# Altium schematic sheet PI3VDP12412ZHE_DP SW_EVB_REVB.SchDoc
size 513 x 386 mm
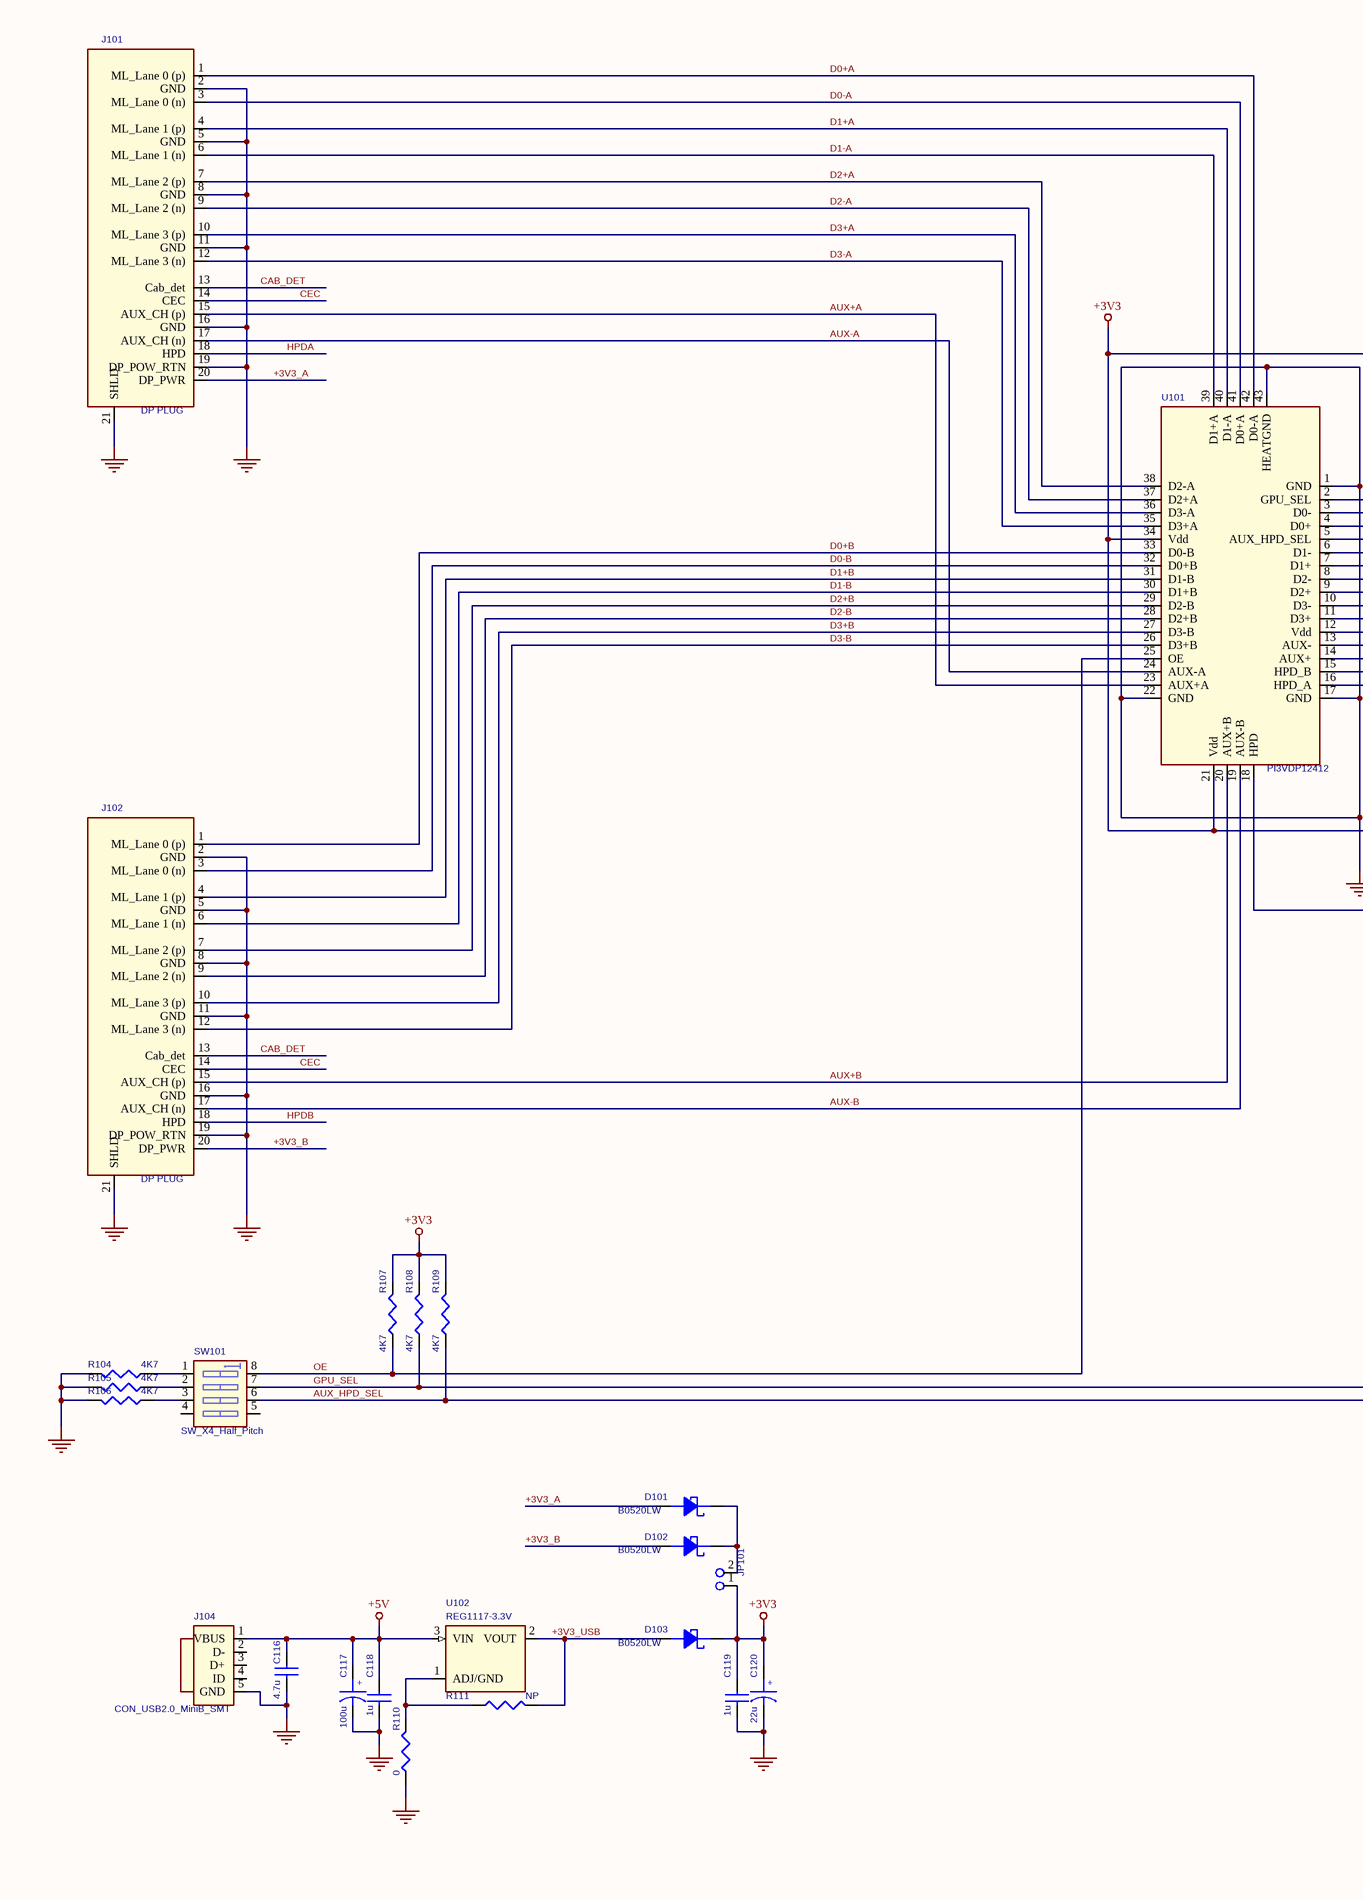
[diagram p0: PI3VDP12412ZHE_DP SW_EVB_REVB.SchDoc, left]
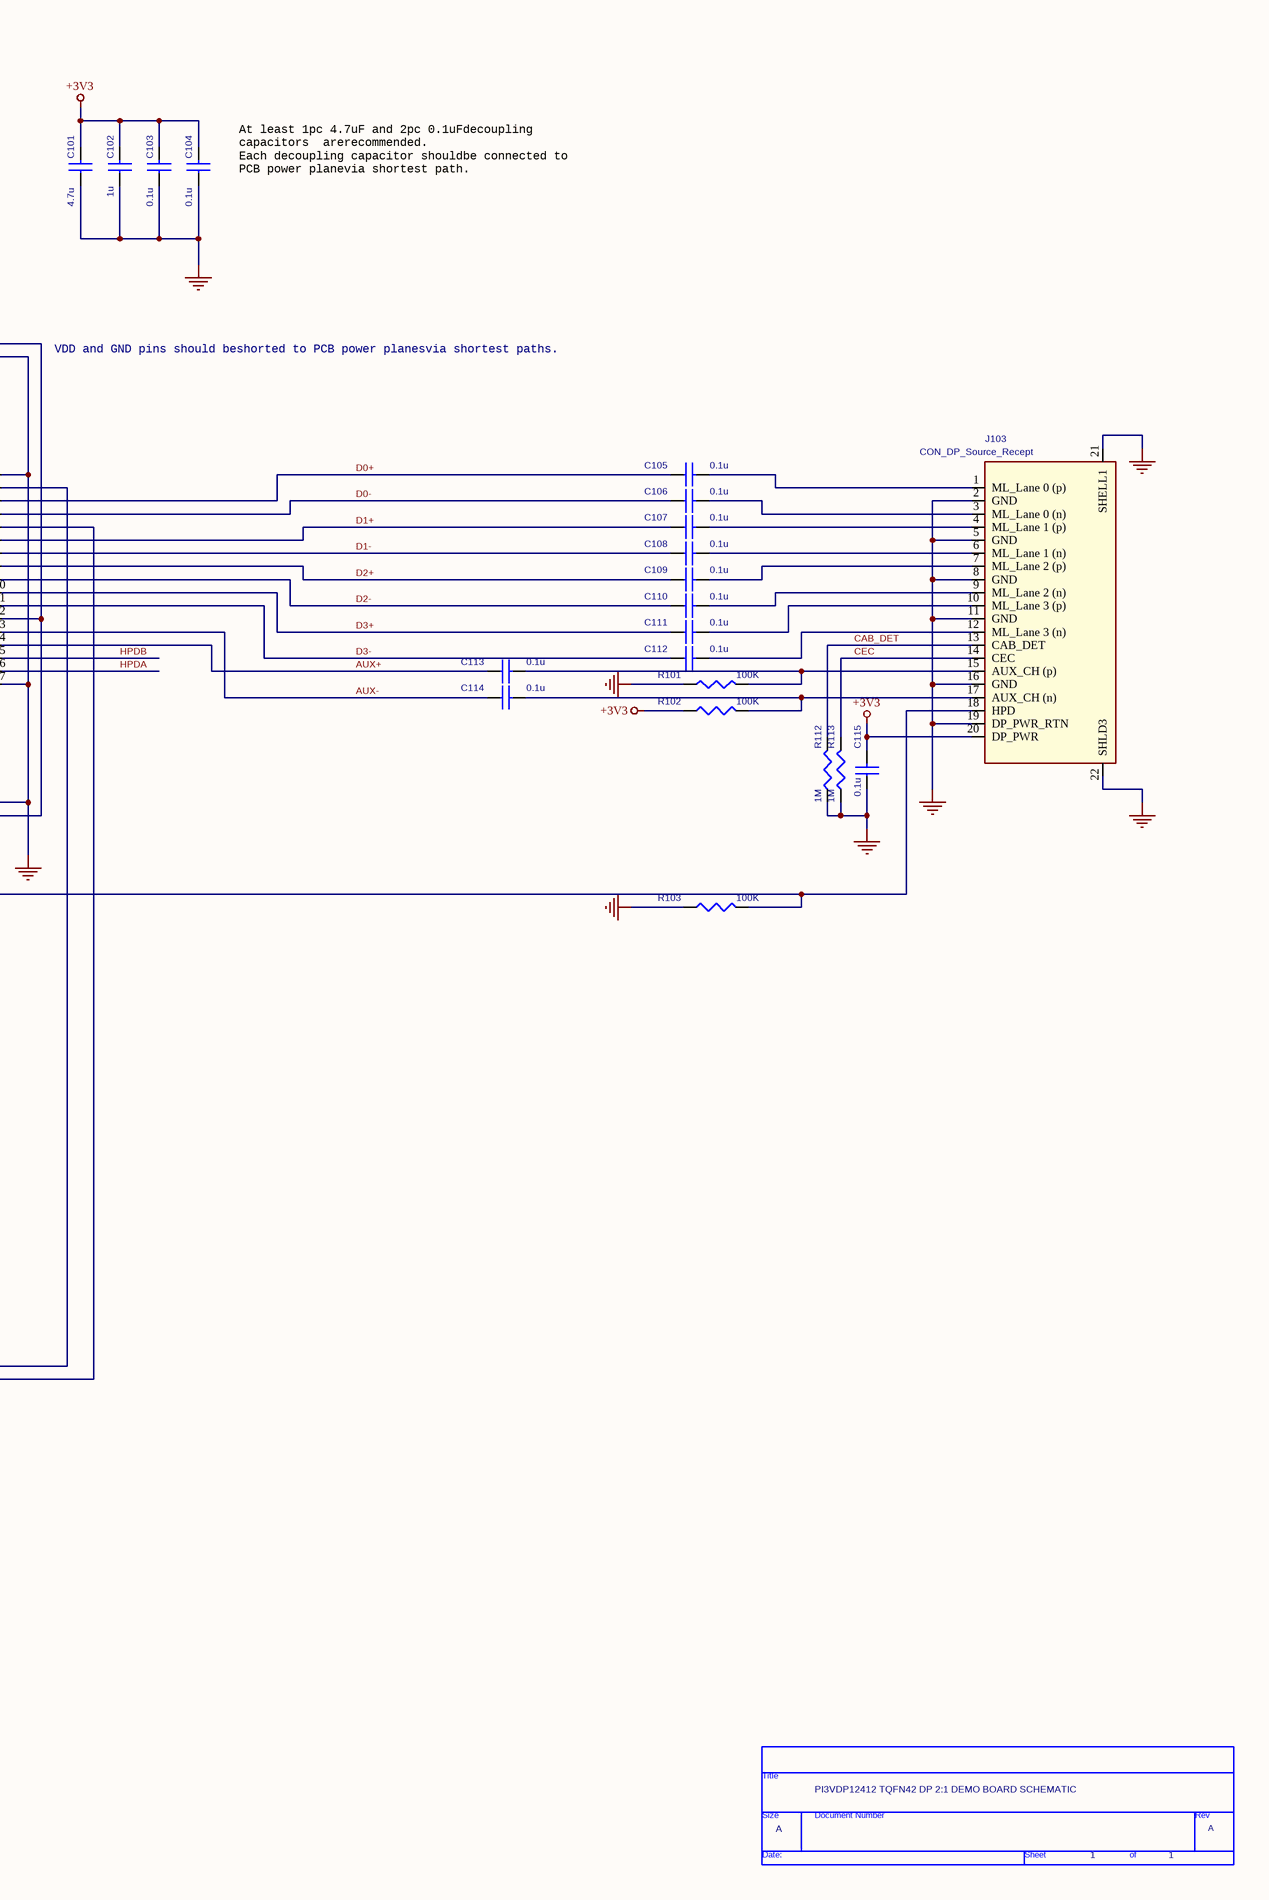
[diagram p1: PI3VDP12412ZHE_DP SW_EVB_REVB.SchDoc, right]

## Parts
*  Page Count: 1  Page Size: A  Title: PI3VDP12412 TQFN42 DP 2:1 DEMO BOARD SCHEMATIC  (hidden comment: TitleBlock0)  (graphical)
C101  4.7u  [CC_0402]
C102  1u  [CC_0402]
C103  0.1u  [CC_0402]
C104  0.1u  [CC_0402]
C105  0.1u  [CC_0402]
C106  0.1u  [CC_0402]
C107  0.1u  [CC_0402]
C108  0.1u  [CC_0402]
C109  0.1u  [CC_0402]
C110  0.1u  [CC_0402]
C111  0.1u  [CC_0402]
C112  0.1u  [CC_0402]
C113  0.1u  [CC_0402]
C114  0.1u  [CC_0402]
C115  0.1u  [CC_0402]
C116  4.7u  [CAP@CC_0805]
C117  100u  [CAP@CT_7343]
C118  1u  [CAP@CC_0805]
C119  1u  [CAP@CC_0805]
C120  22u  [CAP@CT_3528]
D101  B0520LW  [D@SOD-123]
D102  B0520LW  [D@SOD-123]
D103  B0520LW  [D@SOD-123]
J101  DP PLUG  [CON_DP_PLUG]
J102  DP PLUG  [CON_DP_PLUG]
J103  CON_DP_Source_Recept  [CON_DP_Recept]
J104  CON_USB2.0_MiniB_SMT  [CON_USB2.0_MiniB_SMT]
JP101  2x1 Pin Header  [2x1 Pin Header]  (value not drawn)
R101  100K  [R_0402]
R102  100K  [R_0402]
R103  100K  [R_0402]
R104  4K7  [R_0402]
R105  4K7  [R_0402]
R106  4K7  [R_0402]
R107  4K7  [RES@R_0402]
R108  4K7  [RES@R_0402]
R109  4K7  [RES@R_0402]
R110  0  [RES@R_0402]
R111  NP  [RES@R_0402]
R112  1M  [RES@R_0402]
R113  1M  [RES@R_0402]
SW101  SW_X4_Half_Pitch  [SW_X4_Half_Pitch]
U101  PI3VDP12412  [TQFN42]
U102  REG1117-3.3V  [Pow_SOT_89]

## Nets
+3V3: C101.2 C102.2 C103.2 C104.2 C115.2 C119.1 C120.1 D103.2 J103.20(DP_PWR) JP101.1 R102.1 R107.2 R108.2 R109.2 U101.12(Vdd) U101.21(Vdd) U101.34(Vdd)
+5V: C116.1 C117.1 C118.1 J104.1(VBUS) U102.3(VIN)
GND: C101.1 C102.1 C103.1 C104.1 C115.1 C116.2 C117.2 C118.2 C119.2 C120.2 J101.2(GND) J101.5(GND) J101.8(GND) J101.11(GND) J101.16(GND) J101.19(DP_POW_RTN) J101.21(SHLD) J102.2(GND) J102.5(GND) J102.8(GND) J102.11(GND) J102.16(GND) J102.19(DP_POW_RTN) J102.21(SHLD) J103.2(GND) J103.5(GND) J103.8(GND) J103.11(GND) J103.16(GND) J103.19(DP_PWR_RTN) J103.21(SHELL1) J103.22(SHLD3) J104.5(GND) R101.1 R103.1 R104.2 R105.2 R106.2 R110.1 R112.1 R113.1 U101.1(GND) U101.17(GND) U101.22(GND) U101.43(HEATGND)
+3V3_A: D101.1 J101.20(DP_PWR)
+3V3_B: D102.1 J102.20(DP_PWR)
+3V3_USB: D103.1 R111.2 U102.2(VOUT)
AUX+: C113.1 U101.14(AUX+)
AUX+A: J101.15(AUX_CH_(p)) U101.23(AUX+A)
AUX+B: J102.15(AUX_CH_(p)) U101.20(AUX+B)
AUX-: C114.1 U101.13(AUX-)
AUX-A: J101.17(AUX_CH_(n)) U101.24(AUX-A)
AUX-B: J102.17(AUX_CH_(n)) U101.19(AUX-B)
AUX_HPD_SEL: R109.1 SW101.6 U101.5(AUX_HPD_SEL)
CAB_DET: J101.13(Cab_det) J102.13(Cab_det) J103.13(CAB_DET) R112.2
CEC: J101.14(CEC) J102.14(CEC) J103.14(CEC) R113.2
D0+: C105.1 U101.3(D0-)
D0+A: J101.1(ML_Lane_0_(p)) U101.42(D0-A)
D0+B: J102.1(ML_Lane_0_(p)) U101.33(D0-B)
D0-: C106.1 U101.4(D0+)
D0-A: J101.3(ML_Lane_0_(n)) U101.41(D0+A)
D0-B: J102.3(ML_Lane_0_(n)) U101.32(D0+B)
D1+: C107.1 U101.6(D1-)
D1+A: J101.4(ML_Lane_1_(p)) U101.40(D1-A)
D1+B: J102.4(ML_Lane_1_(p)) U101.31(D1-B)
D1-: C108.1 U101.7(D1+)
D1-A: J101.6(ML_Lane_1_(n)) U101.39(D1+A)
D1-B: J102.6(ML_Lane_1_(n)) U101.30(D1+B)
D2+: C109.1 U101.8(D2-)
D2+A: J101.7(ML_Lane_2_(p)) U101.38(D2-A)
D2+B: J102.7(ML_Lane_2_(p)) U101.29(D2-B)
D2-: C110.1 U101.9(D2+)
D2-A: J101.9(ML_Lane_2_(n)) U101.37(D2+A)
D2-B: J102.9(ML_Lane_2_(n)) U101.28(D2+B)
D3+: C111.1 U101.10(D3-)
D3+A: J101.10(ML_Lane_3_(p)) U101.36(D3-A)
D3+B: J102.10(ML_Lane_3_(p)) U101.27(D3-B)
D3-: C112.1 U101.11(D3+)
D3-A: J101.12(ML_Lane_3_(n)) U101.35(D3+A)
D3-B: J102.12(ML_Lane_3_(n)) U101.26(D3+B)
GPU_SEL: R108.1 SW101.7 U101.2(GPU_SEL)
HPDA: J101.18(HPD) U101.16(HPD_A)
HPDB: J102.18(HPD) U101.15(HPD_B)
OE: R107.1 SW101.8 U101.25(OE)
NetC105_2: C105.2 J103.1(ML_Lane_0_(p))
NetC106_2: C106.2 J103.3(ML_Lane_0_(n))
NetC107_2: C107.2 J103.4(ML_Lane_1_(p))
NetC108_2: C108.2 J103.6(ML_Lane_1_(n))
NetC109_2: C109.2 J103.7(ML_Lane_2_(p))
NetC110_2: C110.2 J103.9(ML_Lane_2_(n))
NetC111_2: C111.2 J103.10(ML_Lane_3_(p))
NetC112_2: C112.2 J103.12(ML_Lane_3_(n))
NetC113_2: C113.2 J103.15(AUX_CH_(p)) R101.2
NetC114_2: C114.2 J103.17(AUX_CH_(n)) R102.2
NetD101_2: D101.2 D102.2 JP101.2
NetJ103_18: J103.18(HPD) R103.2 U101.18(HPD)
NetR104_1: R104.1 SW101.1
NetR105_1: R105.1 SW101.2
NetR106_1: R106.1 SW101.3
NetR110_2: R110.2 R111.1 U102.1(ADJ/GND)

Not connected (* = marked no-connect by the designer): J104 2(D-) 3(D+) 4(ID); SW101 4 5

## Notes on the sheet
- (near C104) At least 1pc 4.7uF and 2pc 0.1uFdecoupling capacitors  arerecommended.
  Each decoupling capacitor shouldbe connected to PCB power planevia shortest path.
- VDD and GND pins should beshorted to PCB power planesvia shortest paths.

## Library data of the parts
C101-C115 = C_0.1u_0402
C116 C118 C119 = CHIP CAP0805
C117 = 100UF 7343_1
C120 = 22UF 3528
D101-D103 = SchottkyDiode@SOD-123_1
J101 = CONN_DP_1
J102 = CONN_DP_0
J103 = CON_DP_Source_Recept_1
R101-R106 = R_0402
R107-R113 = CHIP RES0402_1
U101 = PI3PCIE3412ZHE@TQFN42_1
U102 = REG1117ADJ@SOT89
